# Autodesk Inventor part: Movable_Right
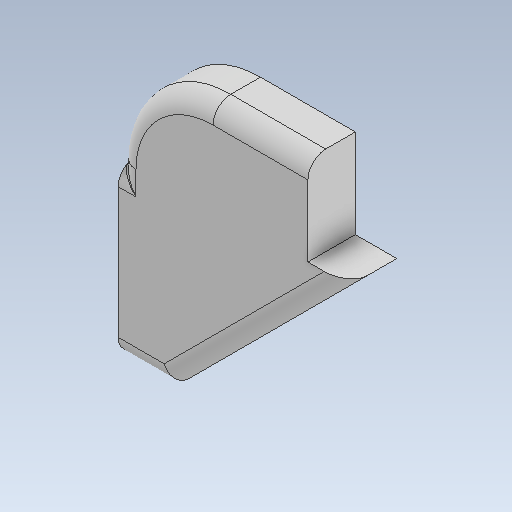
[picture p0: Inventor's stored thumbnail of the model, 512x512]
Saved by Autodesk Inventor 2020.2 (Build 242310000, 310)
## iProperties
Created: 2019-12
Part Number: Movable_Right
Material: Generic
Document SubType Name: Modeling
Designer: Patrick Everitt
Density: 1 g/cm^3
Appearance: Default
Description: 1x6 CRS 5 Lg
Author: Patrick Everitt
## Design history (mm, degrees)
sketch "Sketch1"
  geometry: L1 (-25.4, -3.175)-(-25.4, -50.8); L2 (-25.4, -50.8)-(-3.175, -50.8); L3 (-25.4, -3.175)-(-76.2, -3.175); L4 (-127, -53.975)-(-127, -146.05); L5 (-127, -146.05)-(-98.425, -146.05); L6 (-3.175, -50.8)-(-98.425, -146.05); A1 r 50.8 centre (-76.2, -53.975) between (-76.2, -3.175) and (-127, -53.975); 2 further points
  constraints: 12 end point, 3 horizontal, 2 point on circle, 2 point on line, 2 tangent, 2 vertical, 1 centre point
  dimensions: "d0" = 47.625 distance of L1.start L1.end; "d2" = 22.225 distance of L1.end L2.end; "d4" = 101.6 distance of L1.start point (-127, -3.175); "d6" = 142.875 distance of point (-127, -3.175) L4.end; "d9" = 45 deg angle of L6 L2; "d10" = 50.8 radius of A1
extrude "Extrusion1" new body sketch "Sketch1" distance "d11" = 25.4; taper "d12" = 0 deg
fillet "Fillet1" dims "d13" = 9.525
sketch "Sketch2"
  geometry: L1 (0, 0)-(0, 95.25) reference; L2 (0, 0)-(15.875, 0); L3 (25.4, 9.525)-(25.4, 88.9); L4 (0, 92.075)-(25.4, 92.075) reference; L5 (25.4, 88.9)-(0, 88.9); L6 (15.875, 0)-(15.875, 95.25) reference; L7 (0, 88.9)-(0, 0); A1 r 9.525 centre (15.875, 9.525) between (15.875, 0) and (25.4, 9.525); 5 further points
  constraints: 8 end point, 3 perpendicular, 2 point on circle, 2 point on line, 2 tangent, 1 centre point, 1 horizontal
  dimensions: "d14" = 88.9 distance of point (25.4, 0) L3.end; "d19" = 9.525 radius of A1 (derived); "d21" = 16.6624 distance from line of L3 point (8.738, 25.4); "d22" = 16.6624 distance from line of L3 point (8.738, 63.5) (= d21); "d23" = 25.4 vertical distance of L1.start point (8.738, 25.4) (= d24); "d24" = 25.4 distance from line of L5 point (8.738, 63.5)
extrude "Extrusion2" join sketch "Sketch2" distance "d15" = 0.00025; taper "d16" = 0 deg
fillet "Fillet2" dims "d17" = 9.525
fillet "Fillet3" dims "d18" = 9.525
fillet "Fillet4" dims "d20" = 1.5875
hole "Hole1" sketch "Sketch2" diameter "d25" = 6.4008; stored, may be unused: countersink angle "d29" = 82 deg, drill point angle "d31" = 118 deg; dims "d26" = 15.875, "d27" = 9.525, "d28" = 6.35, "d30" = 22.9362
body "Solid1"
